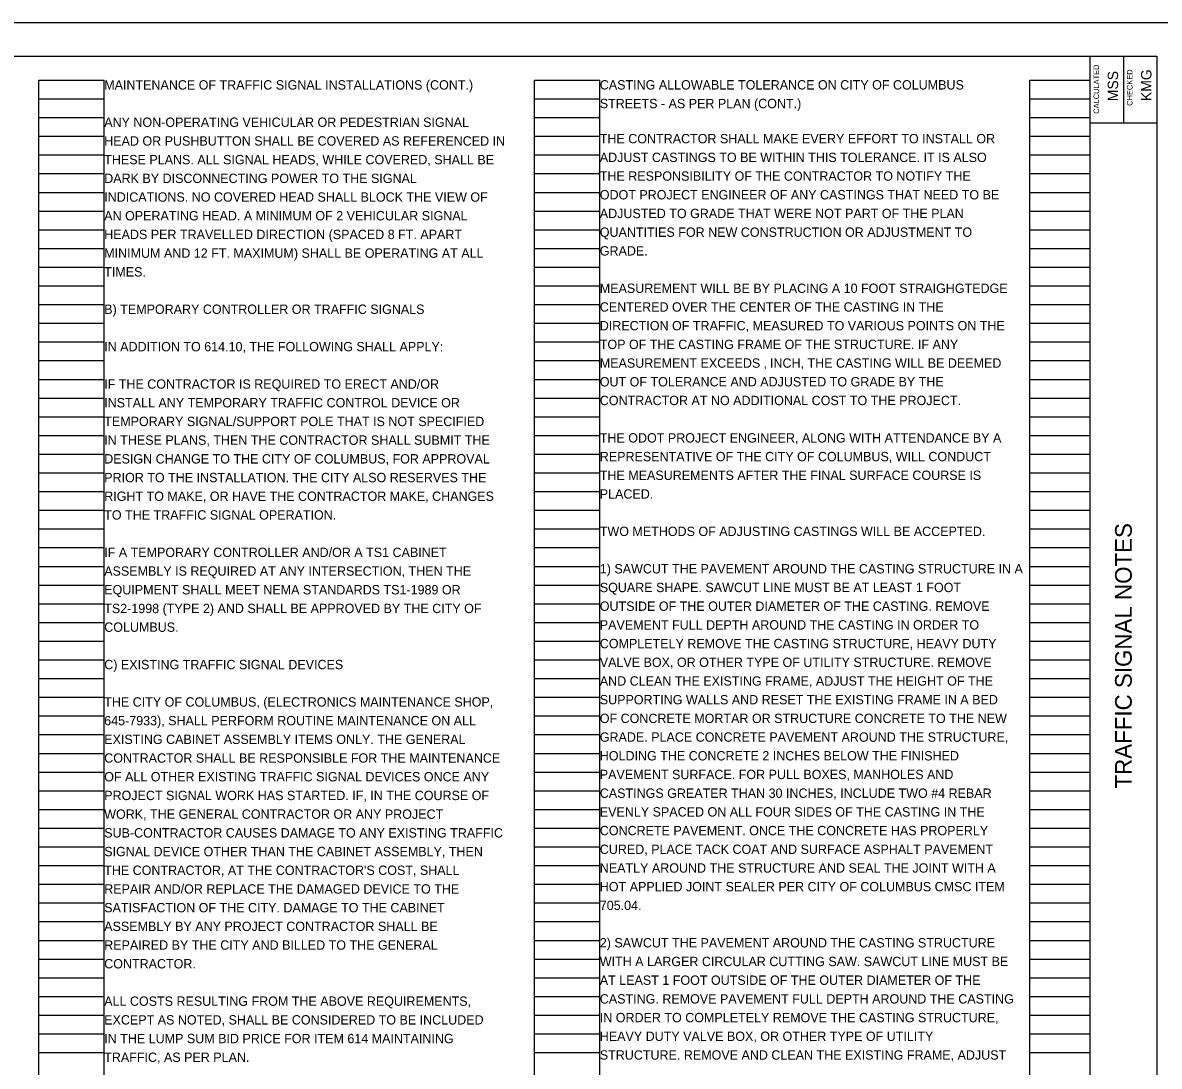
# Model space of a CAD drawing. Extents: x -62 to 50, y -16 to 14.
# Drawn here: x 16.01 to 33.03, y -1.13 to 14.49 of the extents above; entities that cross this region are included whole.
import ezdxf

# ---------------------------------------------------------------- set-up
doc = ezdxf.new("R2010")
doc.units = 0
for name, color, linetype in [('Level 63', 7, 'Continuous'), ('PF_P_Text', 7, 'Continuous'), ('SC_Scratch1', 7, 'Continuous'), ('SH_Cut_Line', 7, 'Continuous'), ('SH_Text', 7, 'Continuous')]:
    doc.layers.add(name, color=color, linetype=linetype)

msp = doc.modelspace()

# ---------------------------------------------------------------- linework, layer by layer
at = {"layer": 'PF_P_Text'}
for p, q in [((31.994, -7.008), (31.994, 13.992)), ((32.494, 13.992), (32.494, 12.992)), ((31.994, 12.992), (32.994, 12.992))]:
    msp.add_line(p, q, dxfattribs=at)
msp.add_lwpolyline([(1.494, 13.992), (32.994, 13.992), (32.994, -7.008), (1.494, -7.008)], close=True, dxfattribs=at)
at = {"layer": 'SC_Scratch1'}
for p, q in [((16.254, -6.528), (16.254, 13.632)), ((16.254, 13.632), (17.234, 13.632)), ((17.234, -6.528), (17.234, 13.632)), ((23.674, -6.528), (23.674, 13.632)), ((23.674, 13.632), (24.654, 13.632)), ((24.654, -6.528), (24.654, 13.632)), ((31.094, -6.528), (31.094, 13.632)), ((31.094, 13.632), (31.994, 13.632)), ((31.994, -6.528), (31.994, 13.632)), ((16.254, 13.352), (17.234, 13.352)), ((23.674, 13.352), (24.654, 13.352)), ((31.094, 13.352), (31.994, 13.352)), ((16.254, 13.072), (17.234, 13.072)), ((23.674, 13.072), (24.654, 13.072)), ((31.094, 13.072), (31.994, 13.072)), ((16.254, 12.792), (17.234, 12.792)), ((23.674, 12.792), (24.654, 12.792)), ((31.094, 12.792), (31.994, 12.792)), ((16.254, 12.512), (17.234, 12.512)), ((23.674, 12.512), (24.654, 12.512)), ((31.094, 12.512), (31.994, 12.512)), ((16.254, 12.232), (17.234, 12.232)), ((23.674, 12.232), (24.654, 12.232)), ((31.094, 12.232), (31.994, 12.232)), ((16.254, 11.952), (17.234, 11.952)), ((23.674, 11.952), (24.654, 11.952)), ((31.094, 11.952), (31.994, 11.952)), ((16.254, 11.672), (17.234, 11.672)), ((23.674, 11.672), (24.654, 11.672)), ((31.094, 11.672), (31.994, 11.672)), ((16.254, 11.392), (17.234, 11.392)), ((23.674, 11.392), (24.654, 11.392)), ((31.094, 11.392), (31.994, 11.392)), ((16.254, 11.112), (17.234, 11.112)), ((23.674, 11.112), (24.654, 11.112)), ((31.094, 11.112), (31.994, 11.112)), ((16.254, 10.832), (17.234, 10.832)), ((23.674, 10.832), (24.654, 10.832)), ((31.094, 10.832), (31.994, 10.832)), ((16.254, 10.552), (17.234, 10.552)), ((23.674, 10.552), (24.654, 10.552)), ((31.094, 10.552), (31.994, 10.552)), ((16.254, 10.272), (17.234, 10.272)), ((23.674, 10.272), (24.654, 10.272)), ((31.094, 10.272), (31.994, 10.272)), ((16.254, 9.992), (17.234, 9.992)), ((23.674, 9.992), (24.654, 9.992)), ((31.094, 9.992), (31.994, 9.992)), ((16.254, 9.712), (17.234, 9.712)), ((23.674, 9.712), (24.654, 9.712)), ((31.094, 9.712), (31.994, 9.712)), ((16.254, 9.432), (17.234, 9.432)), ((23.674, 9.432), (24.654, 9.432)), ((31.094, 9.432), (31.994, 9.432)), ((16.254, 9.152), (17.234, 9.152)), ((23.674, 9.152), (24.654, 9.152)), ((31.094, 9.152), (31.994, 9.152)), ((16.254, 8.872), (17.234, 8.872)), ((23.674, 8.872), (24.654, 8.872)), ((31.094, 8.872), (31.994, 8.872)), ((16.254, 8.592), (17.234, 8.592)), ((23.674, 8.592), (24.654, 8.592)), ((31.094, 8.592), (31.994, 8.592)), ((16.254, 8.312), (17.234, 8.312)), ((23.674, 8.312), (24.654, 8.312)), ((31.094, 8.312), (31.994, 8.312)), ((16.254, 8.032), (17.234, 8.032)), ((23.674, 8.032), (24.654, 8.032)), ((31.094, 8.032), (31.994, 8.032)), ((16.254, 7.752), (17.234, 7.752)), ((23.674, 7.752), (24.654, 7.752)), ((31.094, 7.752), (31.994, 7.752)), ((16.254, 7.472), (17.234, 7.472)), ((23.674, 7.472), (24.654, 7.472)), ((31.094, 7.472), (31.994, 7.472)), ((16.254, 7.192), (17.234, 7.192)), ((23.674, 7.192), (24.654, 7.192)), ((31.094, 7.192), (31.994, 7.192)), ((16.254, 6.912), (17.234, 6.912)), ((23.674, 6.912), (24.654, 6.912)), ((31.094, 6.912), (31.994, 6.912)), ((16.254, 6.632), (17.234, 6.632)), ((23.674, 6.632), (24.654, 6.632)), ((31.094, 6.632), (31.994, 6.632)), ((16.254, 6.352), (17.234, 6.352)), ((23.674, 6.352), (24.654, 6.352)), ((31.094, 6.352), (31.994, 6.352)), ((16.254, 6.072), (17.234, 6.072)), ((23.674, 6.072), (24.654, 6.072)), ((31.094, 6.072), (31.994, 6.072)), ((16.254, 5.792), (17.234, 5.792)), ((23.674, 5.792), (24.654, 5.792)), ((31.094, 5.792), (31.994, 5.792)), ((16.254, 5.512), (17.234, 5.512)), ((23.674, 5.512), (24.654, 5.512)), ((31.094, 5.512), (31.994, 5.512)), ((16.254, 5.232), (17.234, 5.232)), ((23.674, 5.232), (24.654, 5.232)), ((31.094, 5.232), (31.994, 5.232)), ((16.254, 4.952), (17.234, 4.952)), ((23.674, 4.952), (24.654, 4.952)), ((31.094, 4.952), (31.994, 4.952)), ((16.254, 4.672), (17.234, 4.672)), ((23.674, 4.672), (24.654, 4.672)), ((31.094, 4.672), (31.994, 4.672)), ((16.254, 4.392), (17.234, 4.392)), ((23.674, 4.392), (24.654, 4.392)), ((31.094, 4.392), (31.994, 4.392)), ((16.254, 4.112), (17.234, 4.112)), ((23.674, 4.112), (24.654, 4.112)), ((31.094, 4.112), (31.994, 4.112)), ((16.254, 3.832), (17.234, 3.832)), ((23.674, 3.832), (24.654, 3.832)), ((31.094, 3.832), (31.994, 3.832)), ((16.254, 3.552), (17.234, 3.552)), ((23.674, 3.552), (24.654, 3.552)), ((31.094, 3.552), (31.994, 3.552)), ((16.254, 3.272), (17.234, 3.272)), ((23.674, 3.272), (24.654, 3.272)), ((31.094, 3.272), (31.994, 3.272)), ((16.254, 2.992), (17.234, 2.992)), ((23.674, 2.992), (24.654, 2.992)), ((31.094, 2.992), (31.994, 2.992)), ((16.254, 2.712), (17.234, 2.712)), ((23.674, 2.712), (24.654, 2.712)), ((31.094, 2.712), (31.994, 2.712)), ((16.254, 2.432), (17.234, 2.432)), ((23.674, 2.432), (24.654, 2.432)), ((31.094, 2.432), (31.994, 2.432)), ((16.254, 2.152), (17.234, 2.152)), ((23.674, 2.152), (24.654, 2.152)), ((31.094, 2.152), (31.994, 2.152)), ((16.254, 1.872), (17.234, 1.872)), ((23.674, 1.872), (24.654, 1.872)), ((31.094, 1.872), (31.994, 1.872)), ((16.254, 1.592), (17.234, 1.592)), ((23.674, 1.592), (24.654, 1.592)), ((31.094, 1.592), (31.994, 1.592)), ((16.254, 1.312), (17.234, 1.312)), ((23.674, 1.312), (24.654, 1.312)), ((31.094, 1.312), (31.994, 1.312)), ((16.254, 1.032), (17.234, 1.032)), ((23.674, 1.032), (24.654, 1.032)), ((31.094, 1.032), (31.994, 1.032)), ((16.254, 0.752), (17.234, 0.752)), ((23.674, 0.752), (24.654, 0.752)), ((31.094, 0.752), (31.994, 0.752)), ((16.254, 0.472), (17.234, 0.472)), ((23.674, 0.472), (24.654, 0.472)), ((31.094, 0.472), (31.994, 0.472)), ((16.254, 0.192), (17.234, 0.192)), ((23.674, 0.192), (24.654, 0.192)), ((31.094, 0.192), (31.994, 0.192)), ((16.254, -0.088), (17.234, -0.088)), ((23.674, -0.088), (24.654, -0.088)), ((31.094, -0.088), (31.994, -0.088)), ((16.254, -0.368), (17.234, -0.368)), ((23.674, -0.368), (24.654, -0.368)), ((31.094, -0.368), (31.994, -0.368)), ((16.254, -0.648), (17.234, -0.648)), ((23.674, -0.648), (24.654, -0.648)), ((31.094, -0.648), (31.994, -0.648)), ((16.254, -0.928), (17.234, -0.928)), ((23.674, -0.928), (24.654, -0.928)), ((31.094, -0.928), (31.994, -0.928))]:
    msp.add_line(p, q, dxfattribs=at)
at = {"layer": 'SH_Cut_Line'}
msp.add_lwpolyline([(-0.506, -7.508), (33.494, -7.508), (33.494, 14.492), (-0.506, 14.492)], close=True, dxfattribs=at)

# ---------------------------------------------------------------- texts
at = {"layer": 'Level 63'}
for s, height, p in [('CALCULATED', 0.0833, (32.13, 13.129)), ('CHECKED', 0.0833, (32.63, 13.248)), ('MSS', 0.156, (32.414, 13.317)), ('KMG', 0.156, (32.914, 13.319)), ('TRAFFIC SIGNAL NOTES', 0.25, (32.619, 3.025))]:
    msp.add_text(s, height=height, rotation=90, dxfattribs=at).set_placement(p)
at = {"layer": 'SH_Text'}
for s, p in [('MAINTENANCE OF TRAFFIC SIGNAL INSTALLATIONS (CONT.)', (17.234, 13.491)), ('CASTING ALLOWABLE TOLERANCE ON CITY OF COLUMBUS ', (24.654, 13.492)), ('STREETS - AS PER PLAN (CONT.)', (24.654, 13.212)), ('ANY NON-OPERATING VEHICULAR OR PEDESTRIAN SIGNAL ', (17.234, 12.932)), ('HEAD OR PUSHBUTTON SHALL BE COVERED AS REFERENCED IN ', (17.234, 12.652)), ('THE CONTRACTOR SHALL MAKE EVERY EFFORT TO INSTALL OR ', (24.654, 12.686)), ('THESE PLANS. ALL SIGNAL HEADS, WHILE COVERED, SHALL BE ', (17.234, 12.372)), ('ADJUST CASTINGS TO BE WITHIN THIS TOLERANCE. IT IS ALSO ', (24.654, 12.406)), ('THE RESPONSIBILITY OF THE CONTRACTOR TO NOTIFY THE ', (24.654, 12.126)), ('DARK BY DISCONNECTING POWER TO THE SIGNAL ', (17.234, 12.092)), ('INDICATIONS. NO COVERED HEAD SHALL BLOCK THE VIEW OF ', (17.234, 11.812)), ('ODOT PROJECT ENGINEER OF ANY CASTINGS THAT NEED TO BE ', (24.654, 11.846)), ('AN OPERATING HEAD. A MINIMUM OF 2 VEHICULAR SIGNAL ', (17.234, 11.532)), ('ADJUSTED TO GRADE THAT WERE NOT PART OF THE PLAN ', (24.654, 11.566)), ('QUANTITIES FOR NEW CONSTRUCTION OR ADJUSTMENT TO ', (24.654, 11.286)), ('HEADS PER TRAVELLED DIRECTION (SPACED 8 FT. APART ', (17.234, 11.252)), ('MINIMUM AND 12 FT. MAXIMUM) SHALL BE OPERATING AT ALL ', (17.234, 10.972)), ('GRADE. ', (24.654, 11.006)), ('TIMES.', (17.234, 10.692)), ('MEASUREMENT WILL BE BY PLACING A 10 FOOT STRAIGHGTEDGE ', (24.654, 10.446)), ('B) TEMPORARY CONTROLLER OR TRAFFIC SIGNALS ', (17.234, 10.132)), ('CENTERED OVER THE CENTER OF THE CASTING IN THE ', (24.654, 10.166)), ('DIRECTION OF TRAFFIC, MEASURED TO VARIOUS POINTS ON THE ', (24.654, 9.886)), ('IN ADDITION TO 614.10, THE FOLLOWING SHALL APPLY:', (17.234, 9.572)), ('TOP OF THE CASTING FRAME OF THE STRUCTURE. IF ANY ', (24.654, 9.606)), ('MEASUREMENT EXCEEDS ‚ INCH, THE CASTING WILL BE DEEMED ', (24.654, 9.326)), ('IF THE CONTRACTOR IS REQUIRED TO ERECT AND/OR ', (17.234, 9.012)), ('OUT OF TOLERANCE AND ADJUSTED TO GRADE BY THE ', (24.654, 9.046)), ('INSTALL ANY TEMPORARY TRAFFIC CONTROL DEVICE OR ', (17.234, 8.732)), ('CONTRACTOR AT NO ADDITIONAL COST TO THE PROJECT. ', (24.654, 8.766)), ('TEMPORARY SIGNAL/SUPPORT POLE THAT IS NOT SPECIFIED ', (17.234, 8.452)), ('THE ODOT PROJECT ENGINEER, ALONG WITH ATTENDANCE BY A ', (24.654, 8.206)), ('IN THESE PLANS, THEN THE CONTRACTOR SHALL SUBMIT THE ', (17.234, 8.172)), ('DESIGN CHANGE TO THE CITY OF COLUMBUS, FOR APPROVAL ', (17.234, 7.892)), ('REPRESENTATIVE OF THE CITY OF COLUMBUS, WILL CONDUCT ', (24.654, 7.926)), ('PRIOR TO THE INSTALLATION. THE CITY ALSO RESERVES THE ', (17.234, 7.612)), ('THE MEASUREMENTS AFTER THE FINAL SURFACE COURSE IS ', (24.654, 7.646)), ('PLACED. ', (24.654, 7.366)), ('RIGHT TO MAKE, OR HAVE THE CONTRACTOR MAKE, CHANGES ', (17.234, 7.332)), ('TO THE TRAFFIC SIGNAL OPERATION.', (17.234, 7.052)), ('TWO METHODS OF ADJUSTING CASTINGS WILL BE ACCEPTED.', (24.654, 6.806)), ('IF A TEMPORARY CONTROLLER AND/OR A TS1 CABINET ', (17.234, 6.492)), ('ASSEMBLY IS REQUIRED AT ANY INTERSECTION, THEN THE ', (17.234, 6.212)), ('1) SAWCUT THE PAVEMENT AROUND THE CASTING STRUCTURE IN A ', (24.654, 6.246)), ('EQUIPMENT SHALL MEET NEMA STANDARDS TS1-1989 OR ', (17.234, 5.932)), ('SQUARE SHAPE. SAWCUT LINE MUST BE AT LEAST 1 FOOT ', (24.654, 5.966)), ('TS2-1998 (TYPE 2) AND SHALL BE APPROVED BY THE CITY OF ', (17.234, 5.652)), ('OUTSIDE OF THE OUTER DIAMETER OF THE CASTING. REMOVE ', (24.654, 5.686)), ('COLUMBUS.', (17.234, 5.372)), ('PAVEMENT FULL DEPTH AROUND THE CASTING IN ORDER TO ', (24.654, 5.406)), ('COMPLETELY REMOVE THE CASTING STRUCTURE, HEAVY DUTY ', (24.654, 5.126)), ('C) EXISTING TRAFFIC SIGNAL DEVICES ', (17.234, 4.812)), ('VALVE BOX, OR OTHER TYPE OF UTILITY STRUCTURE. REMOVE ', (24.654, 4.846)), ('AND CLEAN THE EXISTING FRAME, ADJUST THE HEIGHT OF THE ', (24.654, 4.566)), ('SUPPORTING WALLS AND RESET THE EXISTING FRAME IN A BED ', (24.654, 4.286)), ('THE CITY OF COLUMBUS, (ELECTRONICS MAINTENANCE SHOP, ', (17.234, 4.252)), ('645-7933), SHALL PERFORM ROUTINE MAINTENANCE ON ALL ', (17.234, 3.972)), ('OF CONCRETE MORTAR OR STRUCTURE CONCRETE TO THE NEW ', (24.654, 4.006)), ('EXISTING CABINET ASSEMBLY ITEMS ONLY. THE GENERAL ', (17.234, 3.692)), ('GRADE. PLACE CONCRETE PAVEMENT AROUND THE STRUCTURE, ', (24.654, 3.726)), ('HOLDING THE CONCRETE 2 INCHES BELOW THE FINISHED ', (24.654, 3.446)), ('CONTRACTOR SHALL BE RESPONSIBLE FOR THE MAINTENANCE ', (17.234, 3.412)), ('OF ALL OTHER EXISTING TRAFFIC SIGNAL DEVICES ONCE ANY ', (17.234, 3.132)), ('PAVEMENT SURFACE. FOR PULL BOXES, MANHOLES AND ', (24.654, 3.166)), ('PROJECT SIGNAL WORK HAS STARTED. IF, IN THE COURSE OF ', (17.234, 2.852)), ('CASTINGS GREATER THAN 30 INCHES, INCLUDE TWO #4 REBAR ', (24.654, 2.886)), ('EVENLY SPACED ON ALL FOUR SIDES OF THE CASTING IN THE ', (24.654, 2.606)), ('WORK, THE GENERAL CONTRACTOR OR ANY PROJECT ', (17.234, 2.572)), ('SUB-CONTRACTOR CAUSES DAMAGE TO ANY EXISTING TRAFFIC ', (17.234, 2.292)), ('CONCRETE PAVEMENT. ONCE THE CONCRETE HAS PROPERLY ', (24.654, 2.326)), ('SIGNAL DEVICE OTHER THAN THE CABINET ASSEMBLY, THEN ', (17.234, 2.012)), ('CURED, PLACE TACK COAT AND SURFACE ASPHALT PAVEMENT ', (24.654, 2.046)), ("THE CONTRACTOR, AT THE CONTRACTOR'S COST, SHALL ", (17.234, 1.732)), ('NEATLY AROUND THE STRUCTURE AND SEAL THE JOINT WITH A ', (24.654, 1.766)), ('REPAIR AND/OR REPLACE THE DAMAGED DEVICE TO THE ', (17.234, 1.452)), ('HOT APPLIED JOINT SEALER PER CITY OF COLUMBUS CMSC ITEM ', (24.654, 1.486)), ('SATISFACTION OF THE CITY. DAMAGE TO THE CABINET ', (17.234, 1.172)), ('705.04.', (24.654, 1.206)), ('ASSEMBLY BY ANY PROJECT CONTRACTOR SHALL BE ', (17.234, 0.892)), ('REPAIRED BY THE CITY AND BILLED TO THE GENERAL ', (17.234, 0.612)), ('2) SAWCUT THE PAVEMENT AROUND THE CASTING STRUCTURE ', (24.654, 0.646)), ('CONTRACTOR.', (17.234, 0.332)), ('WITH A LARGER CIRCULAR CUTTING SAW. SAWCUT LINE MUST BE ', (24.654, 0.366)), ('AT LEAST 1 FOOT OUTSIDE OF THE OUTER DIAMETER OF THE ', (24.654, 0.086)), ('ALL COSTS RESULTING FROM THE ABOVE REQUIREMENTS, ', (17.234, -0.228)), ('CASTING. REMOVE PAVEMENT FULL DEPTH AROUND THE CASTING ', (24.654, -0.194)), ('IN ORDER TO COMPLETELY REMOVE THE CASTING STRUCTURE, ', (24.654, -0.474)), ('EXCEPT AS NOTED, SHALL BE CONSIDERED TO BE INCLUDED ', (17.234, -0.508)), ('IN THE LUMP SUM BID PRICE FOR ITEM 614 MAINTAINING ', (17.234, -0.788)), ('HEAVY DUTY VALVE BOX, OR OTHER TYPE OF UTILITY ', (24.654, -0.754)), ('TRAFFIC, AS PER PLAN.', (17.234, -1.068)), ('STRUCTURE. REMOVE AND CLEAN THE EXISTING FRAME, ADJUST ', (24.654, -1.034))]:
    msp.add_text(s, height=0.14, dxfattribs=at).set_placement(p)

doc.saveas('drawing.dxf')
